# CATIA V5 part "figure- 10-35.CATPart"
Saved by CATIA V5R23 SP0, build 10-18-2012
Part number: Part1
Bounding box of the stored display mesh (mm): x -20 to 20, y -0.339 to 152.641, z -44.55 to 10.195
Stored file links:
  D:\APS\CATIA V5-6R-2013-Project\CATIA V5-6R2013_partfiles\Part_Files\c10_catia_v5-6r2013_prt\figure- 10-35.CATPart
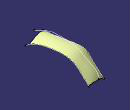
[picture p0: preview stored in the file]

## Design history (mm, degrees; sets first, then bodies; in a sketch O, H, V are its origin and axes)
Set1
  Plane1: type Offset, RefPlane yz-plane, Offset 20, reversed
  Sketch1 on yz-plane, origin (0, 0, 0), H (0, 1, 0), V (0, 0, 1)
    spline S1 through (-0.3393, -8.9363) (20.4957, 1.6782) (43.9804, 9.0119) (85.9797, 8.8277) (110.0875, 1.9736) (113.4186, 0.0053) (148.283, -20.6228) (152.6411, -30.7916)
  Sketch2 on Plane1, origin (-20, 0, 0), H (0, 1, 0), V (0, 0, 1)
    spline S1 through (0, -18.2863) (39.7074, -13.5111) (76.5446, -6.6894) (104.5136, -9.077) (112.3585, -15.8987) (129.7538, -32.6118) (143.3972, -44.5498)
  Plane2: type Offset, RefPlane yz-plane, Offset 20
  Sketch3 on Plane2, origin (20, 0, 0), H (0, 1, 0), V (0, 0, 1)
    spline S1 through (0, -29.0463) (25.3574, -14.3797) (67.652, -5.1704) (115.4039, -10.2866) (140.3031, -31.4339) (148.4891, -38.2556)
  Sweep1: type Conic, Guide ({sweepconicextendedguide Guide Sketch3, Reference Sketch1, Angle 15}; {sweepconicextendedguide Guide Sketch2, Reference Sketch1, Angle 15}), Parameter 0.5
Body1 (main body)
